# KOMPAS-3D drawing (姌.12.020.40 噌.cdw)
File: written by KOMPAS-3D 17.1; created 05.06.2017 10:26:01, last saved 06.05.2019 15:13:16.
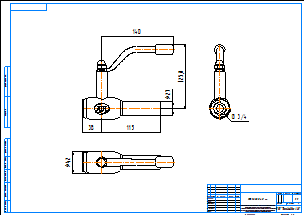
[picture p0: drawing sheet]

Sheet 1: A2, landscape

Title block, sheet 1: name: КШ.12.020.40 рс; material: Внимание! Данный продукт является объектом авторского права ООО «Торговый Дом АДЛ». / Запрещается изменение, копирование, распространение / (в том числе путем копирования на другие сайты и ресурсы в Интернете) / или любое иное использование информации и объектов без предварительного / согласия правообладателя (ООО «Торговый Дом АДЛ»).; sheets: 1; organisation: ООО "Торговый дом АДЛ"; sheet format: A2; stored path: C:\Users\kka\KOMPAS_Work\Модели кранов для исследований\Все краники\Редуцированный резьба-сварка ШК БИВАЛ\КШ.02.015.40 рс.cdw

Views: Вид 1, Проекционный вид 2, Проекционный вид 3
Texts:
  Klimkovich
  ADL
Dimensions and other numbers on the sheet: 115; 38; 140; 27; 125,8; 42; 1:1; 1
